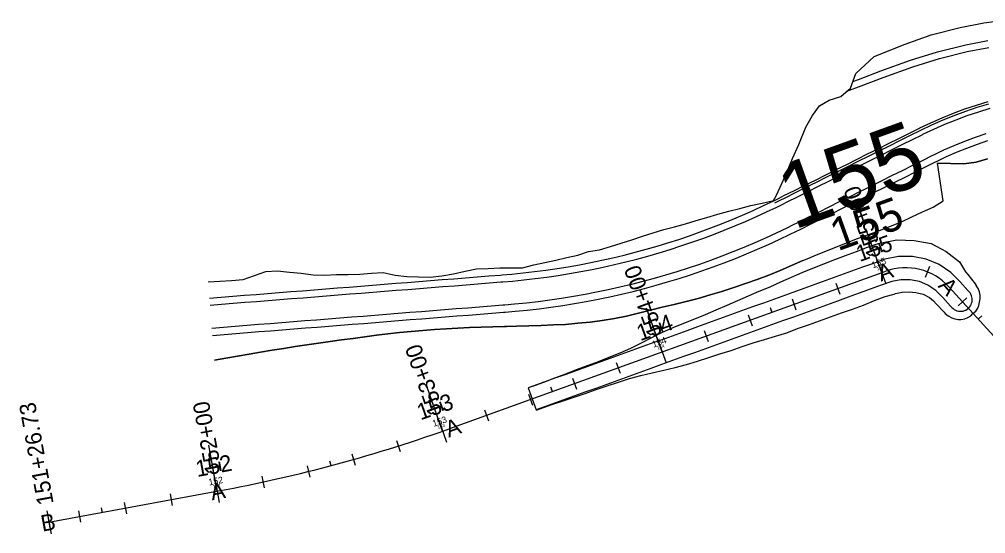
# Model space of a CAD drawing. Extents: x 1823824 to 1861612, y 706975 to 726130.
# Drawn here: x 1825115.5 to 1825529.3, y 715450.1 to 715670.4 of the extents above; entities that cross this region are included whole.
import ezdxf

# ---------------------------------------------------------------- set-up
doc = ezdxf.new("R2010")
doc.units = 0
for name, color, linetype in [('DR_X_Flood_Boundary', 7, 'Continuous'), ('GE_X_CL_10', 7, 'Continuous'), ('GE_X_CL_100', 7, 'Continuous'), ('GE_X_CL_20', 7, 'Continuous'), ('GE_X_CL_200', 7, 'Continuous'), ('GE_X_CL_50', 7, 'Continuous'), ('SC_Scratch1', 7, 'Continuous'), ('SC_Scratch2', 7, 'Continuous'), ('SC_Scratch5', 7, 'Continuous'), ('SC_Scratch6', 7, 'Continuous')]:
    doc.layers.add(name, color=color, linetype=linetype)

msp = doc.modelspace()

# ---------------------------------------------------------------- linework, layer by layer
at = {"layer": 'DR_X_Flood_Boundary'}
for p, q in [((1825301.48, 715495.64), (1825486.59, 715562.46)), ((1825513.59, 715555.77), (1825567.61, 715496.42)), ((1825128.14, 715454.97), (1825200.8, 715468.38))]:
    msp.add_line(p, q, dxfattribs=at)
for centre, radius, start, end in [((1825495.09, 715538.93), 25.02, 42.3061, 109.8494), ((1825085.31, 716094.43), 636.62, 280.45155, 289.84938)]:
    msp.add_arc(centre, radius, start, end, dxfattribs=at)
at = {"layer": 'GE_X_CL_10'}
for p, q in [((1825484.86, 715561.84), (1825484.52, 715562.78)), ((1825437.83, 715544.86), (1825437.49, 715545.8)), ((1825526.15, 715541.97), (1825526.89, 715542.64)), ((1825390.8, 715527.88), (1825390.46, 715528.82)), ((1825343.77, 715510.9), (1825343.43, 715511.85)), ((1825296.74, 715493.95), (1825296.4, 715494.89)), ((1825248.97, 715479.21), (1825248.71, 715480.18)), ((1825200.2, 715468.26), (1825200.02, 715469.25)), ((1825151.03, 715459.19), (1825150.84, 715460.18))]:
    msp.add_line(p, q, dxfattribs=at)
at = {"layer": 'GE_X_CL_100'}
for p, q in [((1825484.86, 715561.84), (1825481.47, 715571.24)), ((1825390.8, 715527.88), (1825387.41, 715537.29)), ((1825296.74, 715493.95), (1825293.42, 715503.38)), ((1825200.2, 715468.26), (1825198.38, 715478.1))]:
    msp.add_line(p, q, dxfattribs=at)
at = {"layer": 'GE_X_CL_20'}
for p, q in [((1825484.86, 715561.84), (1825484.18, 715563.72)), ((1825437.83, 715544.86), (1825437.15, 715546.74)), ((1825526.15, 715541.97), (1825527.63, 715543.31)), ((1825390.8, 715527.88), (1825390.12, 715529.76)), ((1825343.77, 715510.9), (1825343.09, 715512.79)), ((1825296.74, 715493.95), (1825296.07, 715495.83)), ((1825248.97, 715479.21), (1825248.46, 715481.14)), ((1825200.2, 715468.26), (1825199.83, 715470.23)), ((1825151.03, 715459.19), (1825150.66, 715461.16))]:
    msp.add_line(p, q, dxfattribs=at)
at = {"layer": 'GE_X_CL_200'}
for p, q in [((1825484.86, 715561.84), (1825478.07, 715580.65)), ((1825390.8, 715527.88), (1825384.01, 715546.69)), ((1825296.74, 715493.95), (1825290.09, 715512.81)), ((1825200.2, 715468.26), (1825196.57, 715487.93))]:
    msp.add_line(p, q, dxfattribs=at)
at = {"layer": 'GE_X_CL_50'}
for p, q in [((1825484.86, 715561.84), (1825483.16, 715566.54)), ((1825390.8, 715527.88), (1825389.1, 715532.59)), ((1825296.74, 715493.95), (1825295.08, 715498.66)), ((1825200.2, 715468.26), (1825199.29, 715473.18))]:
    msp.add_line(p, q, dxfattribs=at)
at = {"layer": 'SC_Scratch1'}
for points in [[(1825473.77, 715647.11), (1825481.51, 715654.49), (1825494.8, 715659.72), (1825505.99, 715663.76), (1825518.46, 715666.89), (1825528.59, 715668.86), (1825540.4, 715670.37)], [(1825472.49, 715643.74), (1825474.92, 715644.66), (1825484.42, 715648.26), (1825497.21, 715652.93), (1825508.7, 715656.47), (1825520.84, 715659.46), (1825530.29, 715661.26)], [(1825469.89, 715639.54), (1825475.98, 715641.86), (1825485.47, 715645.44), (1825498.16, 715650.08), (1825509.5, 715653.58), (1825521.48, 715656.52), (1825530.76, 715658.3)], [(1825438.51, 715592.73), (1825439.67, 715594.71), (1825441.31, 715598.43), (1825443.97, 715604.52), (1825446.66, 715610.69), (1825449.35, 715616.79), (1825452.29, 715624.22), (1825455.14, 715629.12), (1825458.14, 715633.32), (1825462.3, 715635.68), (1825467.32, 715637.26), (1825471.42, 715640.9), (1825473.77, 715647.11)], [(1825196.9, 715550.96), (1825201.89, 715551.36), (1825206.87, 715551.76), (1825211.85, 715552.15), (1825216.84, 715552.55), (1825221.82, 715552.94), (1825226.81, 715553.34), (1825231.79, 715553.73), (1825236.78, 715554.13), (1825241.76, 715554.52), (1825246.74, 715554.92), (1825251.73, 715555.31), (1825256.71, 715555.71), (1825261.7, 715556.1), (1825266.68, 715556.5), (1825271.67, 715556.89), (1825276.65, 715557.29), (1825281.63, 715557.69), (1825286.62, 715558.08), (1825291.6, 715558.48), (1825296.59, 715558.87), (1825301.57, 715559.27), (1825306.56, 715559.66), (1825311.54, 715560.06), (1825316.53, 715560.45), (1825321.51, 715560.85), (1825322.31, 715560.91), (1825326.39, 715561.26), (1825331.25, 715561.75), (1825336.09, 715562.3), (1825340.93, 715562.93), (1825345.76, 715563.64), (1825350.58, 715564.41), (1825355.38, 715565.26), (1825360.17, 715566.18), (1825364.95, 715567.18), (1825369.71, 715568.24), (1825374.46, 715569.38), (1825379.18, 715570.59), (1825383.89, 715571.87), (1825388.58, 715573.22), (1825393.25, 715574.64), (1825397.89, 715576.13), (1825402.51, 715577.69), (1825407.11, 715579.33), (1825411.69, 715581.03), (1825416.23, 715582.8), (1825420.75, 715584.63), (1825425.24, 715586.54), (1825429.71, 715588.51), (1825434.14, 715590.56), (1825438.54, 715592.66), (1825440.84, 715593.8), (1825442.96, 715594.85), (1825447.44, 715597.08), (1825451.91, 715599.31), (1825456.39, 715601.54), (1825460.86, 715603.77), (1825465.34, 715606), (1825469.82, 715608.23), (1825474.29, 715610.46), (1825478.77, 715612.69), (1825483.24, 715614.92), (1825487.72, 715617.15), (1825492.19, 715619.38), (1825496.67, 715621.6), (1825500.78, 715623.65), (1825501.16, 715623.84), (1825505.9, 715626.1), (1825510.69, 715628.21), (1825515.55, 715630.17), (1825520.47, 715631.99), (1825525.44, 715633.65), (1825530.46, 715635.17)], [(1825197.14, 715547.97), (1825202.12, 715548.37), (1825207.11, 715548.76), (1825212.09, 715549.16), (1825217.08, 715549.56), (1825222.06, 715549.95), (1825227.04, 715550.35), (1825232.03, 715550.74), (1825237.01, 715551.14), (1825242, 715551.53), (1825246.98, 715551.93), (1825251.97, 715552.32), (1825256.95, 715552.72), (1825261.93, 715553.11), (1825266.92, 715553.51), (1825271.9, 715553.9), (1825276.89, 715554.3), (1825281.87, 715554.69), (1825286.86, 715555.09), (1825291.84, 715555.49), (1825296.83, 715555.88), (1825301.81, 715556.28), (1825306.79, 715556.67), (1825311.78, 715557.07), (1825316.76, 715557.46), (1825321.75, 715557.86), (1825322.54, 715557.92), (1825326.67, 715558.27), (1825331.57, 715558.76), (1825336.46, 715559.33), (1825341.34, 715559.96), (1825346.21, 715560.67), (1825351.08, 715561.45), (1825355.93, 715562.31), (1825360.76, 715563.24), (1825365.58, 715564.24), (1825370.39, 715565.32), (1825375.18, 715566.47), (1825379.95, 715567.69), (1825384.7, 715568.98), (1825389.43, 715570.34), (1825394.14, 715571.78), (1825398.83, 715573.28), (1825403.5, 715574.86), (1825408.14, 715576.51), (1825412.75, 715578.22), (1825417.34, 715580.01), (1825421.9, 715581.86), (1825426.44, 715583.79), (1825430.94, 715585.78), (1825435.41, 715587.84), (1825439.86, 715589.97), (1825442.18, 715591.11), (1825444.3, 715592.17), (1825448.78, 715594.4), (1825453.25, 715596.63), (1825457.73, 715598.86), (1825462.2, 715601.09), (1825466.68, 715603.31), (1825471.15, 715605.54), (1825475.63, 715607.77), (1825480.1, 715610), (1825484.58, 715612.23), (1825489.06, 715614.46), (1825493.53, 715616.69), (1825498.01, 715618.92), (1825502.11, 715620.96), (1825502.49, 715621.15), (1825507.14, 715623.37), (1825511.86, 715625.44), (1825516.64, 715627.37), (1825521.47, 715629.16), (1825526.35, 715630.79), (1825531.28, 715632.28)], [(1825438.99, 715591.77), (1825441.29, 715592.9), (1825443.41, 715593.96), (1825447.88, 715596.19), (1825452.36, 715598.42), (1825456.83, 715600.65), (1825461.31, 715602.87), (1825465.78, 715605.1), (1825470.26, 715607.33), (1825474.74, 715609.56), (1825479.21, 715611.79), (1825483.69, 715614.02), (1825488.16, 715616.25), (1825492.64, 715618.48), (1825497.11, 715620.71), (1825501.22, 715622.75), (1825501.62, 715622.95), (1825506.31, 715625.19), (1825511.08, 715627.28), (1825515.91, 715629.24), (1825520.8, 715631.04), (1825525.74, 715632.7), (1825530.73, 715634.2)], [(1825529.39, 715621.27), (1825524.79, 715619.72), (1825520.24, 715618.04), (1825515.75, 715616.23), (1825511.31, 715614.28), (1825506.93, 715612.19), (1825506.57, 715612.01), (1825502.47, 715609.97), (1825497.99, 715607.74), (1825493.51, 715605.51), (1825489.04, 715603.28), (1825484.56, 715601.05), (1825480.09, 715598.82), (1825475.61, 715596.59), (1825471.14, 715594.36), (1825466.66, 715592.13), (1825462.19, 715589.91), (1825457.71, 715587.68), (1825453.23, 715585.45), (1825448.76, 715583.22), (1825446.63, 715582.16), (1825444.24, 715580.98), (1825439.66, 715578.79), (1825435.05, 715576.67), (1825430.41, 715574.61), (1825425.74, 715572.63), (1825421.04, 715570.72), (1825416.31, 715568.88), (1825411.55, 715567.11), (1825406.77, 715565.41), (1825401.96, 715563.79), (1825397.13, 715562.23), (1825392.27, 715560.76), (1825387.4, 715559.35), (1825382.5, 715558.02), (1825377.58, 715556.76), (1825372.65, 715555.58), (1825367.69, 715554.47), (1825362.72, 715553.44), (1825357.74, 715552.48), (1825352.74, 715551.59), (1825347.73, 715550.79), (1825342.71, 715550.06), (1825337.68, 715549.4), (1825332.63, 715548.82), (1825327.58, 715548.32), (1825323.33, 715547.95)], [(1825198.17, 715535.01), (1825203.15, 715535.41), (1825208.13, 715535.81), (1825213.12, 715536.2), (1825218.1, 715536.6), (1825223.09, 715536.99), (1825228.07, 715537.39), (1825233.06, 715537.78), (1825238.04, 715538.18), (1825243.03, 715538.57), (1825248.01, 715538.97), (1825252.99, 715539.36), (1825257.98, 715539.76), (1825262.96, 715540.15), (1825267.95, 715540.55), (1825272.93, 715540.94), (1825277.92, 715541.34), (1825282.9, 715541.74), (1825287.88, 715542.13), (1825292.87, 715542.53), (1825297.85, 715542.92), (1825302.84, 715543.32), (1825307.82, 715543.71), (1825312.81, 715544.11), (1825317.79, 715544.5), (1825322.77, 715544.9), (1825323.57, 715544.96), (1825327.86, 715545.33), (1825332.95, 715545.84), (1825338.04, 715546.42), (1825343.12, 715547.08), (1825348.19, 715547.82), (1825353.24, 715548.64), (1825358.28, 715549.53), (1825363.31, 715550.49), (1825368.33, 715551.54), (1825373.32, 715552.66), (1825378.3, 715553.85), (1825383.26, 715555.12), (1825388.21, 715556.46), (1825393.13, 715557.88), (1825398.02, 715559.37), (1825402.9, 715560.94), (1825407.75, 715562.58), (1825412.58, 715564.29), (1825417.38, 715566.07), (1825422.15, 715567.93), (1825426.89, 715569.86), (1825431.61, 715571.86), (1825436.29, 715573.93), (1825440.94, 715576.07), (1825445.56, 715578.28), (1825447.97, 715579.47), (1825450.1, 715580.53), (1825454.57, 715582.76), (1825459.05, 715584.99), (1825463.52, 715587.22), (1825468, 715589.45), (1825472.47, 715591.68), (1825476.95, 715593.91), (1825481.42, 715596.14), (1825485.9, 715598.37), (1825490.38, 715600.6), (1825494.85, 715602.82), (1825499.33, 715605.05), (1825503.8, 715607.28), (1825507.91, 715609.33), (1825508.26, 715609.5), (1825512.56, 715611.55), (1825516.91, 715613.46), (1825521.32, 715615.25), (1825525.79, 715616.89), (1825530.3, 715618.41)], [(1825451.07, 715567), (1825453.63, 715568.11), (1825455.82, 715569.05), (1825460.48, 715570.91), (1825465.12, 715572.8), (1825469.8, 715574.63), (1825474.47, 715576.47), (1825479.18, 715578.23), (1825483.9, 715579.96), (1825488.56, 715581.83), (1825493.26, 715583.6), (1825497.75, 715585.79), (1825502.28, 715587.91), (1825506.87, 715589.92), (1825511.11, 715592.62), (1825508.67, 715608.73)], [(1825508.67, 715608.73), (1825514.31, 715608.62), (1825519.95, 715608.51), (1825525.2, 715609.19), (1825530.06, 715610.64)], [(1825530.06, 715610.64), (1825525.2, 715609.19), (1825519.95, 715608.51), (1825514.31, 715608.62), (1825508.67, 715608.73)], [(1825511.11, 715592.62), (1825508.67, 715608.73)], [(1825196.36, 715557.89), (1825201.35, 715558.19), (1825206.34, 715558.44), (1825211.32, 715558.98), (1825216.2, 715560.61), (1825221.09, 715562.29), (1825226.08, 715562.6), (1825231.13, 715562.08), (1825236.18, 715561.68), (1825241.25, 715560.96), (1825246.28, 715560.78), (1825251.28, 715561), (1825256.29, 715561.08), (1825261.29, 715561.27), (1825266.28, 715561.57), (1825271.28, 715561.86), (1825276.38, 715560.79), (1825281.44, 715560.16), (1825286.47, 715560.02), (1825291.49, 715559.96), (1825296.46, 715560.5), (1825301.41, 715561.39), (1825306.34, 715562.46), (1825311.27, 715563.49), (1825316.27, 715563.67), (1825321.27, 715563.93), (1825322.06, 715563.98), (1825326.15, 715563.96), (1825331.01, 715563.95), (1825335.75, 715565.14), (1825340.49, 715566.17), (1825345.22, 715567.2), (1825349.93, 715568.28), (1825354.62, 715569.42), (1825359.23, 715570.91), (1825363.98, 715571.7), (1825368.59, 715573.08), (1825373.2, 715574.46), (1825377.78, 715575.93), (1825382.33, 715577.45), (1825386.88, 715578.96), (1825391.49, 715580.28), (1825396.13, 715581.48), (1825400.74, 715582.84), (1825405.35, 715584.19), (1825409.97, 715585.55), (1825414.61, 715586.9), (1825419.28, 715588.19), (1825424.02, 715589.38), (1825428.77, 715590.6), (1825433.62, 715591.66), (1825438.51, 715592.73)], [(1825451.07, 715567), (1825453.63, 715568.11), (1825455.82, 715569.05), (1825460.48, 715570.91), (1825465.12, 715572.8), (1825469.8, 715574.63), (1825474.47, 715576.47), (1825479.18, 715578.23), (1825483.9, 715579.96), (1825488.56, 715581.83), (1825493.26, 715583.6), (1825497.75, 715585.79), (1825502.28, 715587.91), (1825506.87, 715589.92), (1825511.11, 715592.62)], [(1825451.07, 715567), (1825446.18, 715564.94), (1825441.31, 715562.82), (1825436.41, 715560.78), (1825431.43, 715558.94), (1825426.43, 715557.17), (1825421.41, 715555.47), (1825416.37, 715553.85), (1825411.31, 715552.31), (1825406.23, 715550.85), (1825401.13, 715549.46), (1825395.99, 715548.21), (1825390.83, 715547.11), (1825385.74, 715545.73), (1825380.63, 715544.47), (1825375.5, 715543.28), (1825370.35, 715542.19), (1825365.14, 715541.38), (1825359.91, 715540.72), (1825354.67, 715540.2), (1825349.43, 715539.72), (1825344.18, 715539.45), (1825338.93, 715539.22), (1825333.69, 715539.04), (1825328.45, 715538.9), (1825324.06, 715538.82), (1825323.26, 715538.8), (1825318.26, 715538.67), (1825313.25, 715538.5), (1825308.25, 715538.3), (1825303.26, 715538.06), (1825298.26, 715537.78), (1825293.27, 715537.47), (1825288.29, 715537.12), (1825283.3, 715536.7), (1825278.33, 715536.18), (1825273.36, 715535.63), (1825268.39, 715535.04), (1825263.42, 715534.39), (1825258.46, 715533.69), (1825253.5, 715533.05), (1825248.54, 715532.37), (1825243.58, 715531.64), (1825238.62, 715530.94), (1825233.66, 715530.21), (1825228.71, 715529.43), (1825223.75, 715528.63), (1825218.81, 715527.79), (1825213.86, 715526.92), (1825208.91, 715526.08), (1825203.96, 715525.2), (1825199.02, 715524.34)], [(1825199.02, 715524.34), (1825203.96, 715525.2), (1825208.91, 715526.08), (1825213.86, 715526.92), (1825218.81, 715527.79), (1825223.75, 715528.63), (1825228.71, 715529.43), (1825233.66, 715530.21), (1825238.62, 715530.94), (1825243.58, 715531.64), (1825248.54, 715532.37), (1825253.5, 715533.05), (1825258.46, 715533.69), (1825263.42, 715534.39), (1825268.39, 715535.04), (1825273.36, 715535.63), (1825278.33, 715536.18), (1825283.3, 715536.7), (1825288.29, 715537.12), (1825293.27, 715537.47), (1825298.26, 715537.78), (1825303.26, 715538.06), (1825308.25, 715538.3), (1825313.25, 715538.5), (1825318.26, 715538.67), (1825323.26, 715538.8), (1825324.06, 715538.82), (1825328.45, 715538.9), (1825333.69, 715539.04), (1825338.93, 715539.22), (1825344.18, 715539.45), (1825349.43, 715539.72), (1825354.67, 715540.2), (1825359.91, 715540.72), (1825365.14, 715541.38), (1825370.35, 715542.19), (1825375.5, 715543.28), (1825380.63, 715544.47), (1825385.74, 715545.73), (1825390.83, 715547.11), (1825395.99, 715548.21), (1825401.13, 715549.46), (1825406.23, 715550.85), (1825411.31, 715552.31), (1825416.37, 715553.85), (1825421.41, 715555.47), (1825426.43, 715557.17), (1825431.43, 715558.94), (1825436.41, 715560.78), (1825441.31, 715562.82), (1825446.18, 715564.94), (1825451.07, 715567)], [(1825323.33, 715547.95), (1825322.54, 715547.89), (1825317.55, 715547.49), (1825312.57, 715547.1), (1825307.58, 715546.7), (1825302.6, 715546.31), (1825297.62, 715545.91), (1825292.63, 715545.52), (1825287.65, 715545.12), (1825282.66, 715544.73), (1825277.68, 715544.33), (1825272.69, 715543.94), (1825267.71, 715543.54), (1825262.73, 715543.14), (1825257.74, 715542.75), (1825252.76, 715542.35), (1825247.77, 715541.96), (1825242.79, 715541.56), (1825237.8, 715541.17), (1825232.82, 715540.77), (1825227.83, 715540.38), (1825222.85, 715539.98), (1825217.87, 715539.59), (1825212.88, 715539.19), (1825207.9, 715538.8), (1825202.91, 715538.4), (1825197.93, 715538.01)]]:
    msp.add_lwpolyline(points, dxfattribs=at)
at = {"layer": 'SC_Scratch2'}
for points in [[(1825335.43, 715513.21), (1825340.12, 715514.97), (1825344.79, 715516.75), (1825349.46, 715518.53), (1825354.14, 715520.31), (1825358.81, 715522.09), (1825363.48, 715523.87), (1825368.15, 715525.65), (1825372.81, 715527.49), (1825377.4, 715529.49), (1825381.89, 715531.77), (1825386.38, 715534.06), (1825390.88, 715536.33), (1825395.46, 715538.36), (1825400.12, 715540.19), (1825404.74, 715542.12), (1825409.39, 715543.96), (1825413.98, 715545.95), (1825418.58, 715547.94), (1825423.18, 715549.93), (1825427.78, 715551.92), (1825432.37, 715553.91), (1825437, 715555.83), (1825441.57, 715557.88), (1825446.15, 715559.91), (1825450.76, 715561.87), (1825455.37, 715563.83), (1825460.03, 715565.65), (1825464.69, 715567.48), (1825469.37, 715569.23), (1825474.06, 715570.97), (1825478.74, 715572.72), (1825482.42, 715574.01), (1825483.98, 715574.51), (1825491.28, 715575.88), (1825498.67, 715575.65), (1825505.94, 715574.37), (1825512.41, 715570.88), (1825518.14, 715566.48), (1825520.7, 715562.24), (1825521.74, 715561.01), (1825524.82, 715557.06), (1825525.29, 715556.42)], [(1825522.27, 715553.67), (1825521.74, 715554.25), (1825518.37, 715557.95), (1825517.29, 715559.13), (1825514.35, 715561.95), (1825509.4, 715565.32), (1825503.87, 715567.63), (1825498, 715568.81), (1825492.01, 715568.79), (1825486.14, 715567.59), (1825484.9, 715567.17), (1825481.23, 715565.84), (1825476.52, 715564.14), (1825471.82, 715562.45), (1825467.12, 715560.75), (1825462.41, 715559.05), (1825457.71, 715557.35), (1825453.01, 715555.65), (1825448.31, 715553.96), (1825443.6, 715552.26), (1825438.9, 715550.56), (1825434.2, 715548.86), (1825429.49, 715547.17), (1825424.79, 715545.47), (1825420.09, 715543.77), (1825415.38, 715542.07), (1825410.68, 715540.37), (1825405.98, 715538.68), (1825401.28, 715536.98), (1825396.57, 715535.28), (1825391.87, 715533.58), (1825387.17, 715531.89), (1825382.46, 715530.19), (1825377.76, 715528.49), (1825373.06, 715526.79), (1825368.36, 715525.09), (1825363.65, 715523.4), (1825358.95, 715521.7), (1825354.25, 715520), (1825349.54, 715518.3), (1825344.84, 715516.61), (1825340.14, 715514.91), (1825335.43, 715513.21), (1825333.42, 715512.48)], [(1825514.87, 715546.94), (1825514.34, 715547.52), (1825510.97, 715551.22), (1825509.89, 715552.4), (1825507.93, 715554.28), (1825504.63, 715556.53), (1825500.95, 715558.07), (1825497.03, 715558.85), (1825493.04, 715558.84), (1825489.12, 715558.04), (1825488.29, 715557.76), (1825484.62, 715556.43), (1825479.92, 715554.74), (1825475.22, 715553.04), (1825470.51, 715551.34), (1825465.81, 715549.64), (1825461.11, 715547.95), (1825456.4, 715546.25), (1825451.7, 715544.55), (1825447, 715542.85), (1825442.29, 715541.16), (1825437.59, 715539.46), (1825432.89, 715537.76), (1825428.19, 715536.06), (1825423.48, 715534.36), (1825418.78, 715532.67), (1825414.08, 715530.97), (1825409.37, 715529.27), (1825404.67, 715527.57), (1825399.97, 715525.88), (1825395.27, 715524.18), (1825390.56, 715522.48), (1825385.86, 715520.78), (1825381.16, 715519.08), (1825376.45, 715517.39), (1825371.75, 715515.69), (1825367.05, 715513.99), (1825362.34, 715512.29), (1825357.64, 715510.6), (1825352.94, 715508.9), (1825348.24, 715507.2), (1825343.53, 715505.5), (1825338.83, 715503.8), (1825336.82, 715503.08)], [(1825336.84, 715503.02), (1825338.86, 715503.72), (1825343.59, 715505.34), (1825348.33, 715506.94), (1825353.07, 715508.54), (1825357.81, 715510.14), (1825362.54, 715511.75), (1825367.27, 715513.37), (1825372.01, 715514.98), (1825376.78, 715516.48), (1825381.64, 715517.74), (1825386.53, 715518.91), (1825391.43, 715520.09), (1825396.32, 715521.27), (1825401.16, 715522.58), (1825405.97, 715523.97), (1825410.71, 715525.56), (1825415.49, 715527.04), (1825420.27, 715528.53), (1825425, 715530.17), (1825429.75, 715531.74), (1825434.55, 715533.16), (1825439.32, 715534.68), (1825444.12, 715536.11), (1825448.79, 715537.88), (1825453.5, 715539.57), (1825458.2, 715541.27), (1825462.89, 715543), (1825467.59, 715544.71), (1825472.34, 715546.29), (1825477.04, 715547.99), (1825481.67, 715549.87), (1825486.36, 715551.61), (1825490.12, 715552.7), (1825490.74, 715552.88), (1825493.59, 715553.45), (1825496.52, 715553.59), (1825499.49, 715553.32), (1825502.54, 715552.68), (1825505.32, 715551.15), (1825506.94, 715549.72), (1825508.07, 715548.57), (1825511.49, 715544.93), (1825512.05, 715544.37)], [(1825512.05, 715544.37), (1825513.26, 715543.37), (1825514.78, 715542.57), (1825516.15, 715542.07), (1825517.56, 715541.81), (1825518.76, 715541.8), (1825520.36, 715542.09), (1825521.73, 715542.61), (1825522.95, 715543.31), (1825523.9, 715544.43), (1825525.17, 715545.38), (1825525.91, 715546.59), (1825526.38, 715547.83), (1825526.76, 715549.24), (1825526.98, 715550.62), (1825526.95, 715552.28), (1825526.69, 715553.61), (1825526.13, 715555.07), (1825525.29, 715556.42)], [(1825333.42, 715512.48), (1825336.82, 715503.08), (1825336.84, 715503.02)]]:
    msp.add_lwpolyline(points, dxfattribs=at)
msp.add_arc((1825518.57, 715550.3), 5, 222.3089, 42.3102, dxfattribs=at)
at = {"layer": 'SC_Scratch5'}
for points in [[(1825483.16, 715566.54), (1825486.56, 715557.13)], [(1825505.28, 715564.49), (1825503.43, 715559.85)], [(1825465.2, 715557.4), (1825466.9, 715552.69)], [(1825446.39, 715550.61), (1825448.09, 715545.9)], [(1825521.27, 715551.04), (1825517.57, 715547.68)], [(1825427.58, 715543.82), (1825429.27, 715539.11)], [(1825408.76, 715537.02), (1825410.46, 715532.32)], [(1825389.1, 715532.59), (1825392.5, 715523.18)], [(1825371.14, 715523.44), (1825372.84, 715518.74)], [(1825352.33, 715516.65), (1825354.03, 715511.95)], [(1825333.52, 715509.86), (1825335.22, 715505.16)], [(1825314.71, 715503.07), (1825316.4, 715498.37)], [(1825295.08, 715498.66), (1825298.4, 715489.23)], [(1825277.01, 715489.98), (1825278.53, 715485.22)], [(1825257.93, 715484.26), (1825259.29, 715479.45)], [(1825238.68, 715479.14), (1825239.89, 715474.29)], [(1825219.28, 715474.63), (1825220.34, 715469.74)], [(1825199.29, 715473.18), (1825201.1, 715463.35)], [(1825180.08, 715467.1), (1825180.98, 715462.18)], [(1825160.41, 715463.47), (1825161.31, 715458.55)], [(1825127.24, 715459.89), (1825129.05, 715450.06)], [(1825140.74, 715459.84), (1825141.65, 715454.92)], [(1825127.69, 715457.43), (1825128.6, 715452.51)]]:
    msp.add_lwpolyline(points, dxfattribs=at)

# ---------------------------------------------------------------- texts
at = {"layer": 'GE_X_CL_10'}
for s, rotation, p in [('155', 19.8494, (1825482.97, 715562.75)), ('154', 19.8494, (1825388.92, 715528.8)), ('153', 19.3964, (1825294.85, 715494.87)), ('152', 10.4516, (1825198.49, 715469.48))]:
    msp.add_text(s, height=1.4, rotation=rotation, dxfattribs=at).set_placement(p)
at = {"layer": 'GE_X_CL_100'}
msp.add_text('155', height=14, rotation=19.8494, dxfattribs=at).set_placement((1825465.93, 715570.95))
at = {"layer": 'GE_X_CL_20'}
for s, rotation, p in [('155', 19.8494, (1825481.07, 715563.66)), ('154', 19.8494, (1825387.05, 715529.72)), ('153', 19.3964, (1825292.95, 715495.79)), ('152', 10.4516, (1825196.78, 715470.69))]:
    msp.add_text(s, height=2.8, rotation=rotation, dxfattribs=at).set_placement(p)
at = {"layer": 'GE_X_CL_200'}
msp.add_text('155', height=28, rotation=19.8494, dxfattribs=at).set_placement((1825447, 715580.06))
at = {"layer": 'GE_X_CL_50'}
for s, rotation, p in [('155', 19.8494, (1825475.4, 715566.39)), ('154', 19.8494, (1825381.41, 715532.47)), ('153', 19.3964, (1825287.28, 715498.57)), ('152', 10.4516, (1825191.66, 715474.32))]:
    msp.add_text(s, height=7, rotation=rotation, dxfattribs=at).set_placement(p)
at = {"layer": 'SC_Scratch5'}
for s, rotation, p in [('155+00', 109.8494, (1825485.61, 715570.08)), ('154+00', 109.8494, (1825391.55, 715536.13)), ('153+00', 109.3964, (1825297.55, 715502.18)), ('151+26.73', 100.4516, (1825130.22, 715462.98)), ('152+00', 100.4516, (1825202.28, 715476.28))]:
    msp.add_text(s, height=7, rotation=rotation, dxfattribs=at).set_placement(p)
at = {"layer": 'SC_Scratch6'}
for s, rotation, p in [('A', 19.8494, (1825484.49, 715557.98)), ('A', 312.3061, (1825508.65, 715556)), ('A', 19.8494, (1825299.37, 715491.16)), ('A', 10.4516, (1825197.99, 715464.3)), ('B', 10.4516, (1825125.34, 715450.9))]:
    msp.add_text(s, height=7, rotation=rotation, dxfattribs=at).set_placement(p)

doc.saveas('drawing.dxf')
